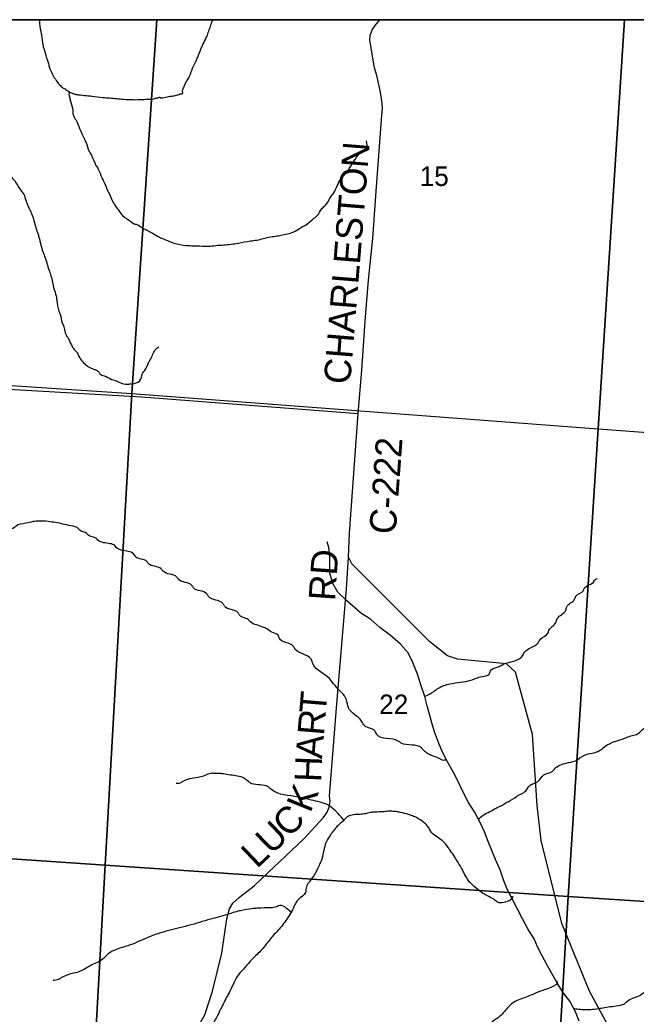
# Model space of a CAD drawing. Extents: x -13.1 to 43.1, y 0 to 22.
# Drawn here: x 3.786 to 5.106, y 18.772 to 20.9 of the extents above; entities that cross this region are included whole.
import ezdxf

# ---------------------------------------------------------------- set-up
doc = ezdxf.new("R2010")
doc.units = 0
for name, color, linetype in [('GM_X_Corporation', 7, 'Continuous'), ('GM_X_County_Road', 7, 'Continuous'), ('GM_X_County_Road_Text', 7, 'Continuous'), ('GM_X_Minor_River', 7, 'Continuous'), ('GM_X_Section_Text', 7, 'Continuous'), ('GM_X_Township_Road', 7, 'Continuous'), ('GM_X_Township_Road_Text', 7, 'Continuous'), ('SH_Data', 7, 'Continuous')]:
    doc.layers.add(name, color=color, linetype=linetype)

msp = doc.modelspace()

# ---------------------------------------------------------------- linework, layer by layer
at = {"layer": 'GM_X_Corporation'}
for points in [[(7.0807, 20.9), (2.1, 20.9), (2.1, 14.1), (6.6193, 14.1), (6.6994, 15.2069), (6.7531, 15.956), (6.8236, 16.9075), (6.9509, 19.0179), (7.0108, 19.8446), (7.0164, 19.8954), (7.0617, 20.6133)], [(7.0804, 20.9), (2.1, 20.9), (2.1, 14.1), (6.619, 14.1), (6.6992, 15.2074), (6.7528, 15.9566), (6.8234, 16.908), (6.8365, 17.1257), (6.9507, 19.0184), (6.9616, 19.1692), (7.0106, 19.8452), (7.0162, 19.896), (7.0615, 20.6138)], [(7.0804, 20.9), (2.1, 20.9), (2.1, 17.2152), (2.1437, 17.2135), (2.8442, 17.1637), (3.8328, 17.0966), (4.4304, 17.0575), (6.8234, 16.908), (6.8365, 17.1257), (6.9507, 19.0184), (6.9616, 19.1692), (7.0106, 19.8452), (7.0162, 19.896), (7.0615, 20.6138)], [(4.0793, 20.9), (3.083, 20.9), (3.0353, 20.1657), (4.0252, 20.1002)], [(5.0812, 20.9), (4.0793, 20.9), (4.0252, 20.1002), (5.0243, 20.0248)], [(6.0839, 20.9), (5.0812, 20.9), (5.0243, 20.0248), (6.0143, 19.9509)], [(3.0353, 20.1657), (4.0252, 20.1002), (3.9684, 19.0905), (2.978, 19.1575)], [(4.0252, 20.1002), (5.0243, 20.0248), (4.9602, 19.0234), (3.9684, 19.0905)], [(5.0243, 20.0248), (6.0143, 19.9509), (5.9495, 18.9594), (4.9602, 19.0234)], [(2.978, 19.1575), (3.9684, 19.0905), (3.9134, 18.1046), (2.9147, 18.1656)], [(3.9684, 19.0905), (4.9602, 19.0234), (4.9031, 18.044), (3.9134, 18.1046)], [(4.9602, 19.0234), (5.9495, 18.9594), (5.8912, 17.9717), (4.9031, 18.044)]]:
    msp.add_lwpolyline(points, close=True, dxfattribs=at)
at = {"layer": 'GM_X_County_Road'}
msp.add_lwpolyline([(5.0689, 18.7047), (5.0057, 18.8205), (4.9465, 18.9653), (4.9023, 19.1435), (4.8935, 19.2182), (4.8836, 19.3704), (4.8472, 19.5038), (4.8278, 19.5218), (4.7231, 19.5312), (4.7019, 19.5386), (4.6638, 19.5686), (4.4966, 19.7353), (4.4896, 19.7499), (4.4915, 19.8011), (4.5102, 20.0575), (4.518, 20.1504), (4.5251, 20.2548), (4.5324, 20.3427), (4.5416, 20.4318), (4.5482, 20.5232), (4.5608, 20.6958), (4.5622, 20.7095), (4.5616, 20.722), (4.5585, 20.7456), (4.5506, 20.781), (4.5452, 20.7974), (4.5354, 20.8568), (4.5363, 20.8666), (4.5406, 20.8787), (4.5464, 20.8878), (4.5569, 20.9)], dxfattribs=at)
at = {"layer": 'GM_X_Minor_River'}
msp.add_lwpolyline([(4.9836, 18.7568), (4.9762, 18.7766), (4.9635, 18.7995), (4.9485, 18.8186), (4.9366, 18.8384), (4.9254, 18.8582), (4.9149, 18.8765), (4.9038, 18.8978), (4.8948, 18.9154), (4.8874, 18.9329), (4.8739, 18.9542), (4.862, 18.9756), (4.8516, 18.9962), (4.8404, 19.0182), (4.8292, 19.0388), (4.8225, 19.0571), (4.8144, 19.0807), (4.8047, 19.1028), (4.7966, 19.1218), (4.7891, 19.1408), (4.781, 19.1621), (4.7706, 19.1835), (4.7594, 19.2048), (4.7467, 19.2246), (4.734, 19.2498), (4.7243, 19.2696), (4.7139, 19.2902), (4.702, 19.3115), (4.6908, 19.3321), (4.6826, 19.3534), (4.6737, 19.3762), (4.6678, 19.3952), (4.6634, 19.4135), (4.6583, 19.4317), (4.6531, 19.4515), (4.645, 19.4743), (4.6376, 19.4994), (4.6272, 19.5246), (4.6175, 19.5451), (4.601, 19.5635), (4.5792, 19.5826), (4.5567, 19.5995), (4.5371, 19.6164), (4.5153, 19.631), (4.4852, 19.657), (4.4664, 19.6746), (4.456, 19.6937), (4.4493, 19.7157), (4.4496, 19.7529), (4.4475, 19.7704), (4.4438, 19.7825)], dxfattribs=at)
for points in [[(3.2976, 20.9), (3.3036, 20.8839), (3.3081, 20.874), (3.3184, 20.8467), (3.3255, 20.8367), (3.3329, 20.8258), (3.3369, 20.8207), (3.3416, 20.8161), (3.3464, 20.813), (3.3514, 20.8103), (3.3713, 20.799), (3.383, 20.7955), (3.4109, 20.7875), (3.4275, 20.7854), (3.4656, 20.7841), (3.4988, 20.7821), (3.509, 20.7804), (3.5407, 20.7713), (3.555, 20.7673), (3.5839, 20.7533), (3.5967, 20.7463), (3.6196, 20.7267), (3.6504, 20.7021), (3.6635, 20.689), (3.6649, 20.6864), (3.6655, 20.6834), (3.666, 20.6803), (3.6672, 20.6776), (3.6715, 20.6738), (3.6767, 20.6707), (3.6818, 20.6677), (3.686, 20.6637), (3.692, 20.6538), (3.7141, 20.6289), (3.725, 20.6189), (3.7303, 20.6124), (3.735, 20.6053), (3.7396, 20.5981), (3.7448, 20.5914), (3.7534, 20.583), (3.7684, 20.5627), (3.7747, 20.5551), (3.7863, 20.5368), (3.7945, 20.5257), (3.7971, 20.5177), (3.806, 20.4953), (3.8105, 20.4858), (3.8201, 20.4546), (3.8245, 20.4413), (3.827, 20.4327), (3.8291, 20.4241), (3.8313, 20.4154), (3.8337, 20.4068), (3.8386, 20.3942), (3.8482, 20.3635), (3.8522, 20.3521), (3.8585, 20.3244), (3.8633, 20.3092), (3.8647, 20.2997), (3.8694, 20.2766), (3.872, 20.2694), (3.8761, 20.2515), (3.8798, 20.2432), (3.8809, 20.2375), (3.8857, 20.2238), (3.8891, 20.2185), (3.8984, 20.1994), (3.9007, 20.1962), (3.9033, 20.1932), (3.9061, 20.1903), (3.9085, 20.1872), (3.9122, 20.1796), (3.9298, 20.1593), (3.9354, 20.1556), (3.9418, 20.153), (3.9482, 20.1506), (3.9539, 20.1472), (3.9572, 20.1422), (3.9659, 20.1383), (3.9817, 20.1302)], [(3.8271, 20.9), (3.8273, 20.8977), (3.8302, 20.8757), (3.832, 20.8666), (3.8328, 20.861), (3.8335, 20.8554), (3.8352, 20.8442), (3.8378, 20.8366), (3.8422, 20.8203), (3.8448, 20.8131), (3.8462, 20.8087), (3.8473, 20.8041), (3.8485, 20.7997), (3.85, 20.7953), (3.853, 20.7895), (3.8582, 20.7774), (3.8619, 20.7728), (3.8687, 20.7628), (3.8724, 20.7594), (3.8807, 20.7528), (3.8841, 20.7513), (3.8886, 20.7482), (3.8961, 20.7436), (3.8998, 20.7424), (3.9063, 20.7404), (3.9112, 20.7399), (3.9281, 20.7378), (3.9398, 20.7369), (3.9636, 20.7339), (3.9779, 20.7329), (4.0081, 20.7302), (4.0493, 20.7297), (4.0549, 20.73), (4.0727, 20.7312), (4.0791, 20.733), (4.0821, 20.7333), (4.0848, 20.7344), (4.0857, 20.7343), (4.0867, 20.7337), (4.0876, 20.7331), (4.0885, 20.7329), (4.101, 20.7354), (4.1142, 20.7371), (4.1184, 20.738), (4.1224, 20.7392), (4.1265, 20.7406), (4.1305, 20.7417), (4.1335, 20.7417), (4.1345, 20.7435), (4.1344, 20.7455), (4.1341, 20.7476), (4.1343, 20.7496), (4.1364, 20.7545), (4.1385, 20.7595), (4.1431, 20.7692), (4.1485, 20.7782), (4.151, 20.7841), (4.1533, 20.7902), (4.1556, 20.7963), (4.1581, 20.8022), (4.1638, 20.8142), (4.1674, 20.8225), (4.1708, 20.8308), (4.1741, 20.8391), (4.1777, 20.8473), (4.1849, 20.862), (4.1893, 20.8728), (4.1931, 20.884), (4.1969, 20.8951), (4.1988, 20.9)], [(3.8912, 20.7466), (3.8908, 20.7406), (3.8922, 20.7338), (3.8941, 20.7258), (3.8988, 20.7061), (3.8992, 20.7004), (3.9044, 20.6875), (3.9077, 20.6825), (3.9133, 20.6677), (3.9163, 20.6616), (3.9192, 20.6544), (3.9271, 20.638), (3.9341, 20.6186), (3.9389, 20.6102), (3.9486, 20.5885), (3.9535, 20.5805), (3.9609, 20.5627), (3.965, 20.5547), (3.9743, 20.533), (3.9791, 20.5238), (3.9888, 20.5033), (3.9952, 20.4949), (4.0094, 20.4776), (4.0169, 20.473), (4.0308, 20.4637), (4.0383, 20.461), (4.0515, 20.4528), (4.0564, 20.4509), (4.0643, 20.4462), (4.0696, 20.4435), (4.0846, 20.4346), (4.0936, 20.4311), (4.1106, 20.424), (4.1219, 20.4205), (4.1494, 20.4167), (4.1637, 20.4165), (4.1894, 20.4157), (4.2053, 20.417), (4.2381, 20.4199), (4.2536, 20.422), (4.2797, 20.4269), (4.2929, 20.4286), (4.3224, 20.4354), (4.3364, 20.4375), (4.3481, 20.4399), (4.3754, 20.4475), (4.3902, 20.4571), (4.3989, 20.4615), (4.4156, 20.4753), (4.422, 20.4805), (4.4335, 20.497), (4.4403, 20.5033), (4.4518, 20.5213), (4.4579, 20.5299), (4.4735, 20.5595), (4.4853, 20.5734), (4.5101, 20.6101), (4.5196, 20.6186), (4.5268, 20.6234), (4.5281, 20.6412)], [(3.9817, 20.1302), (3.9949, 20.1262), (3.9994, 20.1239), (4.0164, 20.1202), (4.0258, 20.1212), (4.0421, 20.1267), (4.0447, 20.1308), (4.0459, 20.1353), (4.0505, 20.1466), (4.0543, 20.1507), (4.0612, 20.1665), (4.065, 20.1721), (4.0754, 20.1935), (4.0833, 20.2002)], [(4.6995, 19.316), (4.6907, 19.3151), (4.6877, 19.3166), (4.6824, 19.3197), (4.6696, 19.3245), (4.6501, 19.3368), (4.6459, 19.3414), (4.6026, 19.3519), (4.5962, 19.3561), (4.5503, 19.3704), (4.5458, 19.378), (4.5247, 19.3885), (4.5176, 19.3988), (4.4895, 19.4272), (4.4851, 19.4443), (4.4608, 19.4749), (4.4488, 19.4898), (4.4139, 19.5209), (4.4094, 19.5316), (4.3756, 19.5525), (4.3711, 19.5594), (4.3418, 19.5757), (4.3388, 19.5825), (4.3253, 19.5891), (4.3144, 19.5965), (4.308, 19.5996), (4.2929, 19.6047), (4.2794, 19.6117), (4.2771, 19.6144), (4.2564, 19.6256), (4.2531, 19.6306), (4.2241, 19.6446), (4.2204, 19.6504), (4.1899, 19.6655), (4.1862, 19.6713), (4.1575, 19.6841), (4.1538, 19.6895), (4.1256, 19.702), (4.1218, 19.707), (4.0921, 19.7199), (4.0884, 19.7245), (4.0609, 19.7362), (4.0575, 19.7408), (4.0338, 19.7506), (4.0308, 19.7548), (4.0079, 19.7642), (3.9917, 19.7708), (3.9887, 19.7746), (3.9789, 19.7786), (3.9529, 19.7865), (3.9499, 19.7896), (3.9311, 19.7978), (3.9288, 19.8005), (3.9134, 19.8075), (3.9115, 19.8105), (3.895, 19.8168), (3.8772, 19.8208), (3.8622, 19.8237), (3.8459, 19.8262), (3.8271, 19.8272), (3.8139, 19.8259), (3.7984, 19.8223), (3.7768, 19.8158), (3.7741, 19.8132), (3.7564, 19.8078), (3.7454, 19.8027), (3.7317, 19.7957), (3.7294, 19.7931), (3.706, 19.784), (3.7026, 19.7806), (3.6715, 19.7674), (3.6431, 19.7531), (3.637, 19.7486), (3.6287, 19.7453), (3.6207, 19.7322), (3.6191, 19.7236), (3.6111, 19.7119), (3.603, 19.689), (3.598, 19.677), (3.5831, 19.6541), (3.5816, 19.6454), (3.5709, 19.6259), (3.5701, 19.6176), (3.5655, 19.6075), (3.5616, 19.5913), (3.5593, 19.5845), (3.5532, 19.5755), (3.5512, 19.5653), (3.5443, 19.556), (3.5272, 19.5392), (3.5257, 19.5343), (3.5169, 19.5238), (3.5161, 19.5189), (3.5119, 19.5118), (3.5084, 19.496), (3.5065, 19.4866), (3.5059, 19.4586)], [(4.6531, 19.4515), (4.6721, 19.4624), (4.6823, 19.4695), (4.7069, 19.4786), (4.7515, 19.4863), (4.7757, 19.4942), (4.7909, 19.4993), (4.7936, 19.5065), (4.8083, 19.5142), (4.8246, 19.5219), (4.8625, 19.5388), (4.8663, 19.5463), (4.8959, 19.5666), (4.8997, 19.5734), (4.9172, 19.5875), (4.9191, 19.5932), (4.934, 19.6103), (4.9367, 19.6182), (4.9553, 19.6365), (4.9572, 19.6437), (4.9739, 19.6597), (4.9762, 19.6657), (4.9929, 19.6787), (4.9952, 19.684), (5.0142, 19.6965), (5.0165, 19.7003), (5.0229, 19.704)], [(4.768, 19.1884), (4.7721, 19.1929), (4.7994, 19.2088), (4.8081, 19.214), (4.8184, 19.2184), (4.8267, 19.2239), (4.8362, 19.2287), (4.8555, 19.2409), (4.8669, 19.2472), (4.8787, 19.2614), (4.895, 19.2695), (4.9083, 19.2836), (4.9261, 19.2913), (4.9314, 19.2969), (4.956, 19.309), (4.9757, 19.3141), (4.9954, 19.3259), (5.0272, 19.3356), (5.0386, 19.3445), (5.0817, 19.3625), (5.0946, 19.3672), (5.1067, 19.3704), (5.1112, 19.373), (5.1223, 19.3827), (5.1404, 19.3888), (5.1454, 19.3929), (5.1609, 19.3995), (5.1685, 19.4017), (5.1757, 19.4069), (5.1851, 19.4086), (5.1878, 19.4093)], [(4.4797, 19.1868), (4.4533, 19.2141), (4.4465, 19.2187), (4.41, 19.2298), (4.3821, 19.2363), (4.3244, 19.2526), (4.3173, 19.2584), (4.2826, 19.2649), (4.2631, 19.2781), (4.2476, 19.2817), (4.2182, 19.2863), (4.2152, 19.2867), (4.2009, 19.2869), (4.1971, 19.2873), (4.1918, 19.2863), (4.1789, 19.2811), (4.1676, 19.2783), (4.132, 19.2682), (4.1282, 19.266), (4.1207, 19.2653)], [(4.8375, 19.0235), (4.8415, 19.0229), (4.8385, 19.0177), (4.8294, 19.0125), (4.815, 19.0097), (4.8105, 19.0105), (4.8034, 19.0155), (4.7981, 19.019), (4.7819, 19.0279), (4.7714, 19.0341), (4.7549, 19.0487), (4.7474, 19.0564), (4.7366, 19.0747), (4.7317, 19.0842), (4.722, 19.1002), (4.7176, 19.1075), (4.7082, 19.1212), (4.703, 19.1285), (4.6902, 19.143), (4.6655, 19.1631), (4.661, 19.1714), (4.652, 19.1814), (4.6291, 19.195), (4.6182, 19.1989), (4.6008, 19.2033), (4.5937, 19.2049), (4.5823, 19.2058), (4.5767, 19.2059), (4.5653, 19.2049), (4.5601, 19.2046), (4.5551, 19.2043), (4.5487, 19.2037), (4.5397, 19.2038), (4.537, 19.2031), (4.5306, 19.2017), (4.5261, 19.2006), (4.5143, 19.1992), (4.5072, 19.199), (4.4939, 19.1965), (4.4886, 19.1947), (4.4818, 19.1891), (4.478, 19.185), (4.4708, 19.1787), (4.4674, 19.1753), (4.4639, 19.172), (4.4552, 19.1615), (4.451, 19.1551), (4.443, 19.1424), (4.4399, 19.1349), (4.4356, 19.1172), (4.4325, 19.1036), (4.4283, 19.0938), (4.418, 19.0724), (4.4054, 19.0545), (4.3996, 19.044), (4.3973, 19.0323), (4.3821, 19.0166), (4.3679, 18.9915), (4.3595, 18.9783), (4.3409, 18.9533), (4.3306, 18.9425), (4.3135, 18.9212), (4.3039, 18.9096), (4.2834, 18.8894), (4.2751, 18.8801), (4.2602, 18.8633), (4.2537, 18.8558), (4.2449, 18.8401), (4.2407, 18.8311), (4.2312, 18.8127), (4.2266, 18.8044), (4.2193, 18.7894), (4.2155, 18.7819), (4.2078, 18.7661), (4.2036, 18.7586), (4.1956, 18.7413), (4.191, 18.7316), (4.1802, 18.7094), (4.1738, 18.6985), (4.1585, 18.6768), (4.1479, 18.6671), (4.1293, 18.6515), (4.1107, 18.6435), (4.1054, 18.6386), (4.0895, 18.6324), (4.0766, 18.6209), (4.0622, 18.6139), (4.0526, 18.5989), (4.0397, 18.5851), (4.037, 18.5776), (4.0362, 18.5723), (4.0339, 18.567), (4.0316, 18.555), (4.0296, 18.5478), (4.025, 18.5294), (4.023, 18.5165), (4.016, 18.492)], [(4.3667, 18.9896), (4.3393, 19.0032), (4.3355, 19.0014), (4.3227, 18.9993), (4.2947, 18.9982), (4.2827, 18.9972), (4.2611, 18.9937), (4.2498, 18.9909), (4.221, 18.9822), (4.1998, 18.9765), (4.1529, 18.9628), (4.1276, 18.9563), (4.0815, 18.9437), (4.0584, 18.935), (4.0167, 18.9178), (3.9743, 18.8999), (3.9671, 18.8928), (3.9565, 18.8846), (3.9428, 18.8784), (3.9303, 18.8714), (3.905, 18.86), (3.8902, 18.8565), (3.883, 18.8532), (3.8796, 18.8521), (3.8735, 18.8487), (3.8682, 18.8458), (3.8569, 18.8433)], [(4.9723, 18.7836), (4.9867, 18.7819), (4.9928, 18.7814), (5.0245, 18.7836), (5.0377, 18.7857), (5.0721, 18.7909), (5.0808, 18.7938), (5.0854, 18.7982), (5.1134, 18.8118), (5.1293, 18.8226), (5.1532, 18.8298), (5.1846, 18.843), (5.2061, 18.8483), (5.213, 18.8524), (5.2361, 18.8661), (5.2478, 18.8727), (5.2626, 18.8763), (5.2815, 18.8854), (5.2891, 18.8937), (5.3127, 18.9134), (5.3316, 18.921), (5.3369, 18.9244)], [(4.9331, 18.8445), (4.9369, 18.8404), (4.9233, 18.8289), (4.8968, 18.8191), (4.874, 18.8096), (4.8434, 18.7968), (4.8335, 18.7886), (4.8133, 18.7662), (4.7932, 18.7506), (4.7875, 18.7408), (4.7666, 18.7177), (4.7491, 18.7066), (4.7343, 18.6883), (4.7176, 18.6738), (4.7126, 18.6621), (4.6946, 18.6287), (4.6858, 18.6126), (4.68, 18.587), (4.6731, 18.5765), (4.6696, 18.5595), (4.6673, 18.5508), (4.6604, 18.5339), (4.6543, 18.5249), (4.6523, 18.5182), (4.6447, 18.502), (4.6393, 18.4934), (4.6354, 18.4791), (4.6305, 18.4712), (4.6213, 18.4498), (4.6182, 18.4415), (4.614, 18.4317), (4.6083, 18.4265), (4.5965, 18.4157), (4.5912, 18.4143), (4.5886, 18.4143)]]:
    msp.add_spline(points, degree=3, dxfattribs=at)
at = {"layer": 'GM_X_Township_Road'}
for points in [[(3.4438, 20.1288), (3.5132, 20.124), (4.0459, 20.0927), (4.5102, 20.0575)], [(4.3421, 19.0978), (4.3947, 19.1475), (4.4352, 19.1921), (4.4437, 19.2041), (4.448, 19.2147), (4.4501, 19.2272), (4.4487, 19.2386), (4.4644, 19.4355), (4.4853, 19.682), (4.4896, 19.7499)], [(4.0363, 18.6432), (4.0593, 18.6562), (4.1, 18.6879), (4.1283, 18.7073), (4.1425, 18.7189), (4.1556, 18.7331), (4.1699, 18.7489), (4.1819, 18.77), (4.1986, 18.821), (4.2183, 18.9023), (4.2288, 18.9755), (4.2316, 18.9861), (4.2344, 18.9971), (4.2418, 19.0091), (4.256, 19.0218), (4.2878, 19.0461), (4.3313, 19.0876), (4.3421, 19.0978)]]:
    msp.add_lwpolyline(points, dxfattribs=at)
at = {"layer": 'SH_Data'}
msp.add_line((2.1, 20.9), (8.9, 20.9), dxfattribs=at)

# ---------------------------------------------------------------- texts
at = {"layer": 'GM_X_County_Road_Text'}
for s, rotation, p in [('CHARLESTON', 85.3728, (4.4931, 20.1187)), ('C-222', 85.8754, (4.5906, 19.7976))]:
    msp.add_text(s, height=0.05682, rotation=rotation, dxfattribs=at).set_placement(p)
at = {"layer": 'GM_X_Section_Text'}
for s, p in [('15', (4.6421, 20.5444)), ('22', (4.5554, 19.4138))]:
    msp.add_text(s, height=0.04186, rotation=0, dxfattribs=at).set_placement(p)
at = {"layer": 'GM_X_Township_Road_Text'}
for s, height, rotation, p in [('RD', 0.05682, 86.0547, (4.4607, 19.6551)), ('T', 0.0568, 85.2738, (4.4408, 19.4135)), ('R', 0.0568, 85.2642, (4.4369, 19.3669)), ('A', 0.0568, 85.2736, (4.4328, 19.3171)), ('H', 0.0568, 87.7913, (4.4309, 19.2678)), ('K', 0.0568, 68.0487, (4.4078, 19.2006)), ('C', 0.0568, 45.5663, (4.3619, 19.1471)), ('U', 0.0568, 43.6771, (4.3243, 19.1111)), ('L', 0.0568, 43.5725, (4.2934, 19.0817))]:
    msp.add_text(s, height=height, rotation=rotation, dxfattribs=at).set_placement(p)

doc.saveas('drawing.dxf')
